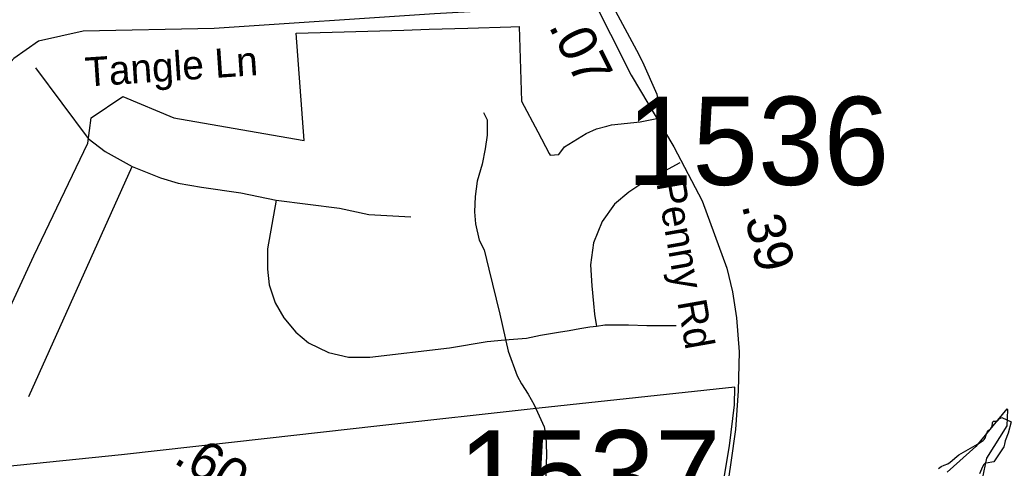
# Model space of a CAD drawing. Extents: x 1662474 to 1856135, y 779280 to 917889.
# Drawn here: x 1715301 to 1718539, y 821073 to 822536 of the extents above; entities that cross this region are included whole.
import ezdxf

# ---------------------------------------------------------------- set-up
doc = ezdxf.new("R2010")
doc.units = 0
for name, color, linetype in [('Cogo Default Point CELL', 7, 'Continuous'), ('Exist Boundary Political City Limit New Hole', 7, 'Continuous'), ('Exist Hydrographic Lake Shore', 7, 'Continuous'), ('Exist Hydrographic Misc Water Feature', 7, 'Continuous'), ('Exist Road Non-System Type 51', 7, 'Continuous'), ('Exist Road Secondary Mileage Tenths English Label', 7, 'Continuous'), ('Exist Road Secondary Type 51 Attributed', 7, 'Continuous'), ('Exist Road Secondary Type 51 Label', 7, 'Continuous'), ('Map Preparation Boundary City Limit Buffer Line', 7, 'Continuous'), ('Old_Level_44', 7, 'Continuous'), ('Prop DGN Element Guardrail', 7, 'Continuous')]:
    doc.layers.add(name, color=color, linetype=linetype)

msp = doc.modelspace()

# ---------------------------------------------------------------- linework, layer by layer
at = {"layer": 'Exist Boundary Political City Limit New Hole'}
for points in [[(1715534.6, 822215.9), (1715637.4, 822285.6), (1715804.4, 822216.4), (1716023.1, 822178.2), (1716229.9, 822142.2), (1716203.9, 822492.2), (1716555.6, 822502.8), (1716638.2, 822505.3), (1716764, 822509.1), (1716905.4, 822513.3), (1716931.6, 822514.1), (1716940, 822271.2), (1716993.4, 822170.2), (1717030.6, 822099.8), (1717033.4, 822094.5), (1717061.5, 822096.7), (1717080.2, 822121.4), (1717150.8, 822165.4), (1717185.2, 822180.4), (1717218.6, 822188.9), (1717234.2, 822192.9), (1717326.9, 822203.6), (1717398.4, 822216.9), (1717394.8, 822234.2), (1717386, 822277.2), (1717382.8, 822292.6), (1717336, 822398.5), (1717335.4, 822399.9), (1717316.1, 822436.2), (1717263.4, 822535.6), (1717216.6, 822622.8)], [(1715121.2, 821279.2), (1715346.6, 821766.2), (1715523.5, 822133.9), (1715534.6, 822215.9)], [(1717590.8, 820976.4), (1717619.2, 821145.9), (1717635.9, 821279.1), (1717636.6, 821337), (1716996.9, 821267.9), (1716467.6, 821209.5), (1716108.9, 821169.9), (1715633.1, 821116.5), (1715153.5, 821066.9)]]:
    msp.add_lwpolyline(points, dxfattribs=at)
at = {"layer": 'Exist Hydrographic Lake Shore'}
msp.add_lwpolyline([(1718301.8, 821071.5), (1718310.9, 821077.8), (1718319.9, 821082.5), (1718331.9, 821087.2), (1718339.8, 821092.2), (1718361, 821110.6), (1718367.9, 821115.8), (1718375.2, 821120.6), (1718428.5, 821150.8), (1718447.6, 821163.4), (1718451.1, 821166.5), (1718453.8, 821170.2), (1718457.1, 821181.7), (1718461, 821189.6), (1718465.2, 821195.4), (1718472.6, 821202.2), (1718475, 821205.6), (1718476.5, 821209), (1718477.9, 821220.8), (1718479.1, 821224.2), (1718481.2, 821225.8), (1718482.2, 821226.3), (1718488.9, 821225.8), (1718492.8, 821226.6), (1718495.8, 821228.7), (1718500.1, 821233.2), (1718504.1, 821236.1), (1718508.2, 821237.9), (1718539, 821224.1), (1718529.5, 821186.9), (1718519, 821162.1), (1718517.2, 821151), (1718514.9, 821141.8), (1718482, 821092.8), (1718457.1, 821088.8), (1718453.1, 821087.5), (1718450.2, 821084.9), (1718445, 821076.8), (1718435.1, 821054.2)], dxfattribs=at)
at = {"layer": 'Exist Hydrographic Misc Water Feature'}
msp.add_lwpolyline([(1716815.6, 822233.5), (1716827.3, 822209.4), (1716827.2, 822159.4), (1716820.9, 822115.2), (1716811, 822065.4), (1716794.6, 822009.9), (1716788.2, 821959.1), (1716786, 821909.1), (1716789.9, 821869.7), (1716801.7, 821816.9), (1716817.4, 821785.4), (1716833.3, 821722.7), (1716868.7, 821575.1), (1716896.1, 821454.7), (1716925.8, 821374.5), (1716940, 821348), (1716961.8, 821313.9), (1716981.6, 821279.8), (1717013.4, 821207.8), (1717019.1, 821178.2), (1717020.9, 821119.8), (1717016.3, 820937.8)], dxfattribs=at)
at = {"layer": 'Exist Road Non-System Type 51'}
msp.add_line((1715330.9, 821306.1), (1715667.9, 822057), dxfattribs=at)
for points in [[(1715352.9, 822379.2), (1715524.4, 822149.2), (1715580, 822105.9), (1715667.9, 822057)], [(1717456.4, 822069.5), (1717383.2, 822029.2), (1717335.5, 822003.6), (1717290.1, 821973.6), (1717243.6, 821934.4), (1717203.2, 821877.8), (1717174.6, 821808.2), (1717165.1, 821736.9), (1717169.1, 821667.5), (1717175.4, 821610.5), (1717178.4, 821575.8), (1717183.9, 821541.1), (1717184.6, 821536.6)], [(1715667.9, 822057), (1715760.2, 822019.9), (1715818.4, 822003.4), (1715894.6, 821989.8), (1716023.1, 821971.4), (1716138.2, 821947.8)], [(1716138.2, 821947.8), (1716110.4, 821788.8), (1716110.2, 821721.8), (1716116, 821671), (1716135.5, 821611.9), (1716163.1, 821563.2), (1716202.9, 821516.5), (1716244.6, 821482.2), (1716309.1, 821450.4), (1716374.9, 821435.1), (1716444.5, 821434.9), (1716704.2, 821464.9), (1716827.4, 821485.9), (1716884.8, 821491), (1716956.4, 821497.2), (1717002.2, 821506.7), (1717060.9, 821516.9), (1717095.1, 821521.9), (1717130.5, 821528.2), (1717162.6, 821533.7), (1717184.6, 821536.6)], [(1716138.2, 821947.8), (1716345.4, 821921.9), (1716440.6, 821900.6), (1716578.5, 821893)], [(1717184.6, 821536.6), (1717212, 821540.1), (1717251.5, 821540.1), (1717289.6, 821540.1), (1717349, 821538.4), (1717385.5, 821537.9), (1717445.2, 821538.4)]]:
    msp.add_lwpolyline(points, dxfattribs=at)
at = {"layer": 'Exist Road Secondary Type 51 Attributed'}
for points in [[(1717163.3, 822624.6), (1717076.5, 822604.4), (1716947.1, 822572.1), (1716656, 822555.9), (1715936.4, 822507.4), (1715507.8, 822499.3), (1715362.3, 822467), (1715281.4, 822410.4), (1715216.7, 822337.7), (1715103.5, 822119.5), (1714869, 821650.8), (1714763.9, 821489.1), (1714602.2, 821392.2)], [(1717163.3, 822624.6), (1717297.4, 822355.7), (1717437.3, 822121.5), (1717530.1, 821945.4), (1717610.5, 821725.9), (1717629.1, 821648.7), (1717641.4, 821563.4), (1717650.7, 821452.1), (1717647.6, 821325.4), (1717638.3, 821198.7), (1717622.9, 821090.5), (1717601.2, 820942.2), (1717553.7, 820699.2)]]:
    msp.add_lwpolyline(points, dxfattribs=at)
at = {"layer": 'Map Preparation Boundary City Limit Buffer Line'}
for points in [[(1715534.6, 822215.9), (1715637.4, 822285.6), (1715804.4, 822216.4), (1716023.1, 822178.2), (1716229.9, 822142.2), (1716203.9, 822492.2), (1716555.6, 822502.8), (1716638.2, 822505.3), (1716764, 822509.1), (1716905.4, 822513.3), (1716931.6, 822514.1), (1716940, 822271.2), (1716993.4, 822170.2), (1717030.6, 822099.8), (1717033.4, 822094.5), (1717061.5, 822096.7), (1717080.2, 822121.4), (1717150.8, 822165.4), (1717185.2, 822180.4), (1717218.6, 822188.9), (1717234.2, 822192.9), (1717326.9, 822203.6), (1717398.4, 822216.9), (1717394.8, 822234.2), (1717386, 822277.2), (1717382.8, 822292.6), (1717336, 822398.5), (1717335.4, 822399.9), (1717316.1, 822436.2), (1717263.4, 822535.6), (1717216.6, 822622.8)], [(1715121.2, 821279.2), (1715346.6, 821766.2), (1715523.5, 822133.9), (1715534.6, 822215.9)], [(1717590.8, 820976.4), (1717619.2, 821145.9), (1717635.9, 821279.1), (1717636.6, 821337), (1716996.9, 821267.9), (1716467.6, 821209.5), (1716108.9, 821169.9), (1715633.1, 821116.5), (1715153.5, 821066.9)]]:
    msp.add_lwpolyline(points, dxfattribs=at)
at = {"layer": 'Old_Level_44'}
msp.add_lwpolyline([(1718430.7, 820970.4), (1718459.8, 821105.2), (1718525.8, 821210.7), (1718528, 821262.5), (1718524.5, 821266.1), (1718423.4, 821143.2), (1718329.9, 821059.6)], dxfattribs=at)

# ---------------------------------------------------------------- texts
at = {"layer": 'Cogo Default Point CELL'}
for s, p in [('1536', (1717283.7, 821997.2)), ('1537', (1716732.9, 820908.4))]:
    msp.add_text(s, height=288, dxfattribs=at).set_placement(p)
at = {"layer": 'Exist Road Secondary Mileage Tenths English Label'}
for s, rotation, p in [('.39', 283.5028, (1717658.6, 821931.2)), ('.60', 327.5542, (1715799.3, 821092.8))]:
    msp.add_text(s, height=125, rotation=rotation, dxfattribs=at).set_placement(p)
at = {"layer": 'Exist Road Secondary Type 51 Label'}
for s, rotation, p in [('Tangle Ln', 3.8498, (1715517.5, 822318.1)), ('Penny Rd', 279.9863, (1717379.8, 822005))]:
    msp.add_text(s, height=95, rotation=rotation, dxfattribs=at).set_placement(p)
at = {"layer": 'Prop DGN Element Guardrail'}
msp.add_text('.07', height=125, rotation=296.498, dxfattribs=at).set_placement((1717026.7, 822515.9))

doc.saveas('drawing.dxf')
